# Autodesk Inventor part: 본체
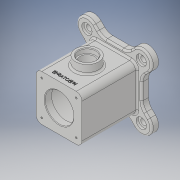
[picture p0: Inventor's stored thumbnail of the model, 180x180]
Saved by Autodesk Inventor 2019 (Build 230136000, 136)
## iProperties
Created: 2021-01
Part Number: 본체
Material: 일반
Document SubType Name: Modeling
Designer: 3dpro0
Density: 1 g/cm^3
Appearance: 기본값
Mass: 385.865 g
Surface Area: 854.376 cm^2
Volume: 385.865 cm^3
Author: 3dpro0
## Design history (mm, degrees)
sketch "스케치1"
  geometry: L1 (-40, -40)-(40, -40); L2 (40, -40)-(40, 40); L3 (40, 40)-(-40, 40); L4 (-40, 40)-(-40, -40); L5 (-40, -40)-(40, 40); L6 (40, -40)-(-40, 40); 1 further point
  constraints: 12 end point, 2 midpoint, 2 parallel, 1 horizontal, 1 perpendicular
  dimensions: "d0" = 80 distance of L3.end L2.end; "d1" = 80 distance of L2.end L1.end
extrude "돌출1" new body sketch "스케치1" distance "d2" = 108; taper "d3" = 0 deg
sketch "스케치2"
  geometry: L1 (-48, -48)-(48, -48); L2 (48, -48)-(48, 48); L3 (48, 48)-(-48, 48); L4 (-48, 48)-(-48, -48); L5 (-48, -48)-(48, 48); L6 (48, -48)-(-48, 48); 1 further point
  constraints: 12 end point, 2 midpoint, 2 parallel, 1 horizontal, 1 perpendicular
  dimensions: "d4" = 96 distance of L3.end L2.end; "d5" = 96 distance of L2.end L1.end
extrude "돌출2" join sketch "스케치2" distance "d6" = 12; taper "d7" = 0 deg
sketch "스케치3"
  geometry: L1 (48, 48)-(-48, 48) reference; L2 (48, -48)-(48, 48) reference; L3 (0, 0)-(47.376, 47.376); L4 (0, 0)-(67, 0); L5 (34.648, 60.104)-(22.544, 48); L6 (60.104, 34.648)-(48, 22.544); A1 r 18 centre (47.376, 47.376) between (60.104, 34.648) and (34.648, 60.104)
  constraints: 8 end point, 2 point on circle, 2 point on line, 2 tangent, 1 centre point, 1 coincident, 1 equal length, 1 horizontal, 1 parallel
  dimensions: "d8" = 67 distance of L3.start L3.end; "d9" = 45 deg angle of L4 L3; "d10" = 36 diameter of A1
extrude "돌출3" join sketch "스케치3" distance "d11" = 12; taper "d12" = 0 deg
sketch "스케치4"
  geometry: C1 r 25 at (0, 0); 1 further point
  constraints: 1 centre point, 1 coincident
  dimensions: "d16" = 50 diameter of C1
extrude "돌출4" cut sketch "스케치4" extent not by distance; stored distance "d17" = 12; taper "d18" = 0 deg
node "작업 평면1"
sketch "스케치5"
  geometry: C1 r 35 at (0, 0); 1 further point
  constraints: 1 centre point, 1 coincident
  dimensions: "d20" = 70 diameter of C1
extrude "돌출5" cut sketch "스케치5" distance "d21" = 84; taper "d22" = 0 deg
sketch "스케치6"
  geometry: L1 (62.544, 108)-(17.456, 108) reference; C1 r 20 at (40, 49); 2 further points
  constraints: 1 centre point, 1 midpoint, 1 vertical alignment
  dimensions: "d23" = 40 diameter of C1; "d24" = 59 distance from line of C1.centre L1
extrude "돌출6" join sketch "스케치6" distance "d25" = 15; taper "d26" = 0 deg
sketch "스케치7"
  geometry: C1 r 20 at (0, 0) reference; 2 further points
  constraints: 1 coincident
hole "구멍1" sketch "스케치7" at (0, 0) diameter "d27" = 25; stored, may be unused: countersink angle "d31" = 90 deg, drill point angle "d33" = 118 deg; dims "d28" = 8, "d29" = 30, "d30" = 8, "d32" = 10
sketch "스케치8"
  geometry: L1 (-30, -30)-(30, -30); L2 (30, -30)-(30, 30); L3 (30, 30)-(-30, 30); L4 (-30, 30)-(-30, -30); L5 (-30, -30)-(30, 30); L6 (30, -30)-(-30, 30); 4 further points
  constraints: 12 end point, 3 coincident, 2 midpoint, 2 parallel, 1 horizontal, 1 perpendicular
  dimensions: "d34" = 60 distance of L3.end L2.end; "d35" = 60 distance of L2.end L1.end
hole "구멍2" sketch "스케치8" at (30, -30), (-30, -30), (30, 30), (-30, 30) diameter "d36" = 3.242; stored, may be unused: countersink angle "d40" = 90 deg, drill point angle "d42" = 118 deg; dims "d37" = 8, "d38" = 30, "d39" = 8, "d41" = 10
node "작업 평면2"
sketch "스케치9"
  geometry: L1 (80, 0)-(0, 0) reference; L2 (62.544, 108)-(17.456, 108) reference; 3 further points
  constraints: 1 midpoint, 1 vertical alignment, 1 other
  dimensions: "d44" = 10 distance from line of L1 point (40, 10)
feature "엠보싱1" sketch "스케치9" dims "d0" = 80, "d1" = 80, "d9" = 45 deg, "d45" = 0.5, "d46" = 0
sketch "스케치10"
  geometry: A1 r 18 centre (47.376, 47.376) between (60.104, 34.648) and (34.648, 60.104) reference; 2 further points
  constraints: 1 coincident
hole "구멍3" sketch "스케치10" at (47.376, 47.376) diameter "d47" = 10; stored, may be unused: countersink angle "d51" = 90 deg, drill point angle "d53" = 118 deg; dims "d48" = 8, "d49" = 18, "d50" = 4, "d52" = 10
fillet "모깎기1" dims "d57" = 10
fillet "모깎기2" dims "d58" = 20
fillet "모깎기3" dims "d59" = 3
chamfer "모따기1" distance "d60" = 1; stored, may be unused: second distance "d61" = 2, angle "d62" = 45 deg
node "솔리드1"
pattern_circular "원형 패턴1" dims angle "d14" = 360 deg
mirror "미러1"
pattern_circular "원형 패턴2" dims angle "d55" = 360 deg
other parameters: "d19" = -12, "d43" = -54
